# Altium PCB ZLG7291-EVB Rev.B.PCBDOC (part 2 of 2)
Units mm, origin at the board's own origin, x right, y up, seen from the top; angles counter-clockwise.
Board outline 90 x 60 mm, 2 copper layers (Top Layer, Bottom Layer); 77 components, 55 nets, 304 pads, 258 vias.
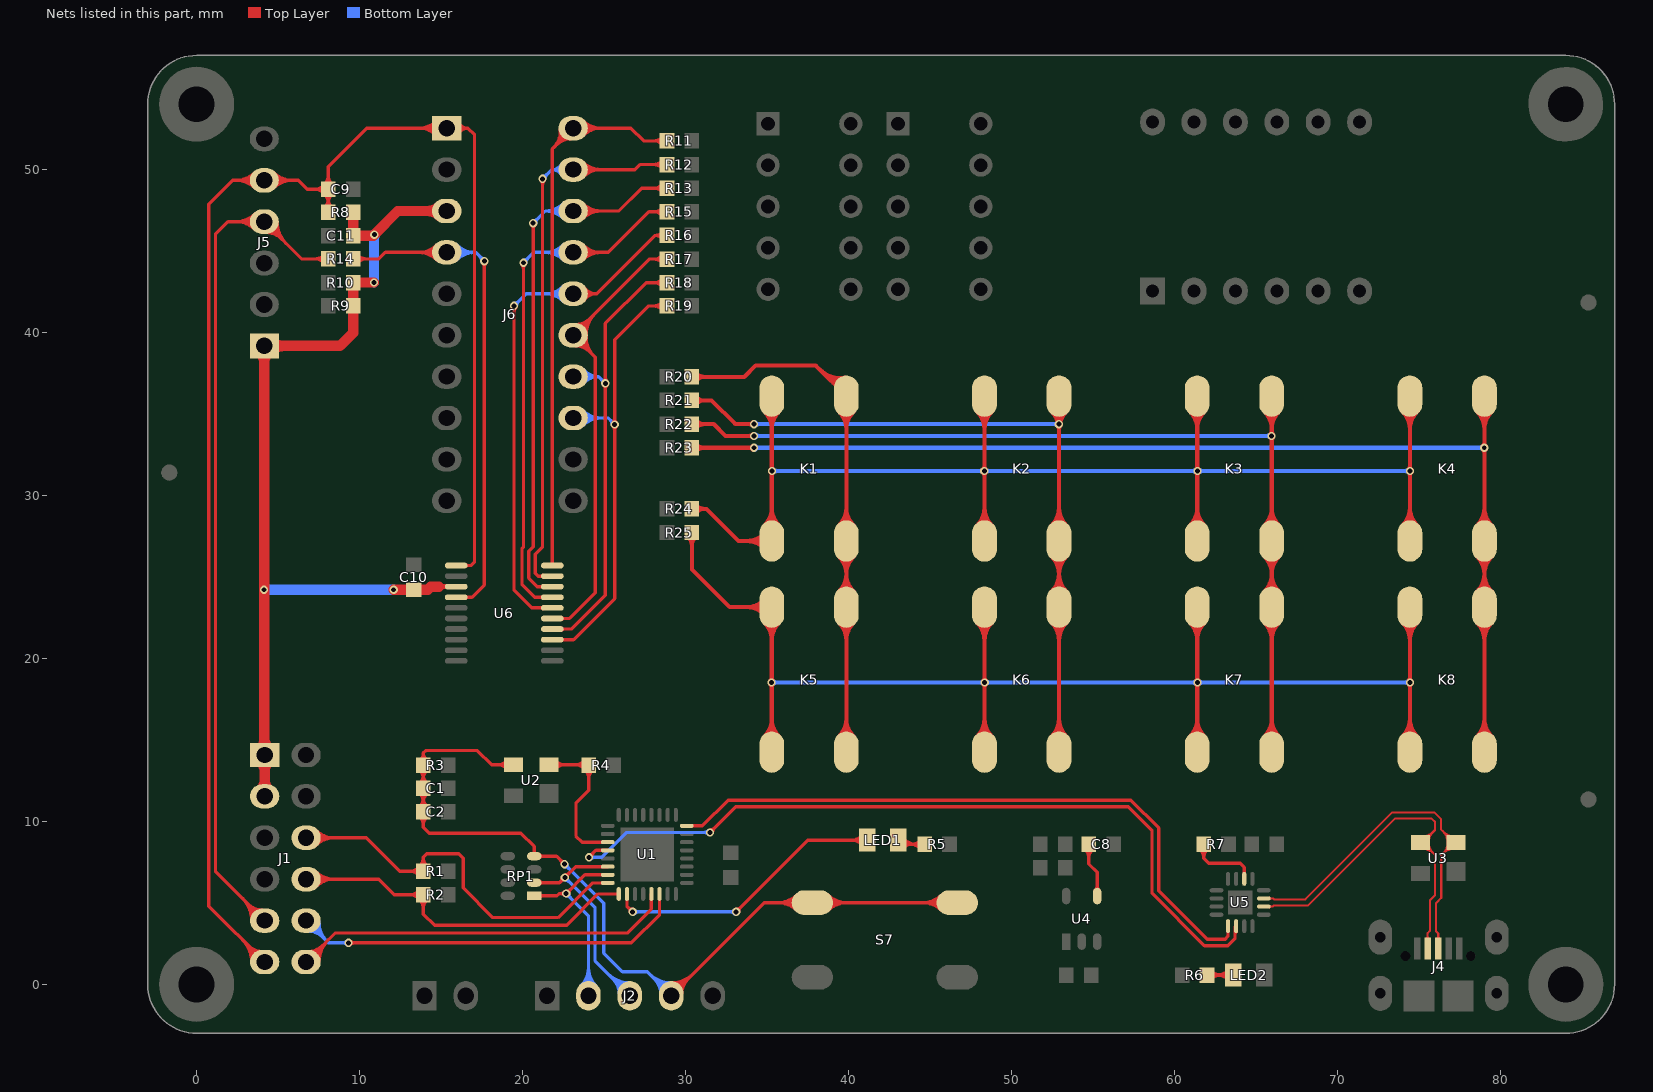
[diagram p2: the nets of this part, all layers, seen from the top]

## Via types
v1: diameter 0.508, hole 0.305, Top Layer to Bottom Layer, tented both sides, 258 vias

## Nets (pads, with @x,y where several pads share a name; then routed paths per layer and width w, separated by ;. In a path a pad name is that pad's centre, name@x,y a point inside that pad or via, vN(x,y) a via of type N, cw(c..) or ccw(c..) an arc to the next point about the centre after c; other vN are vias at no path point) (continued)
J_NRST: C1.2 C2.1 J2.4 R3.1 RP1.4 S7.2 S7.3 U2.3 | length 85.8
  Top Layer w0.203: C2.1@13.667,10.329 cw(c13.072,9.734) 13.913,9.734 cw(c14.754,9.734) C2.1@14.159,10.329 ; C2.1@13.667,10.871 ccw(c13.072,11.466) 13.913,11.466 ccw(c14.754,11.466) C2.1@14.159,10.871 ; C1.2@13.667,11.754 cw(c13.072,11.159) 13.913,11.159 cw(c14.754,11.159) C1.2@14.159,11.754 ; C1.2@13.667,12.296 ccw(c13.072,12.891) 13.913,12.891 ccw(c14.754,12.891) C1.2@14.159,12.296 ; R3.1@13.667,13.179 cw(c13.072,12.584) 13.913,12.584 cw(c14.754,12.584) R3.1@14.159,13.179 ; R3.1@13.695,13.747 ccw(c13.333,14.2) 13.913,14.2 ; R3.1@14.131,13.747 cw(c14.493,14.2) 13.913,14.2 ; U2.3@19.054,13.226 ccw(c18.447,12.619) 18.447,13.478 ccw(c18.447,14.336) U2.3@19.054,13.729 ; U2.3@19.433,13.478 18.098,13.478 17.225,14.35 14.063,14.35 13.913,14.2 ; RP1.4@20.605,7.977 ccw(c20.345,8.237) 20.713,8.237 ccw(c21.081,8.237) RP1.4@20.821,7.977 ; RP1.4@21.011,7.761 cw(c21.271,7.501) 21.271,7.869 cw(c21.271,8.237) RP1.4@21.011,7.977 ; v1@22.423,7.375 ccw(c22.055,7.375) 22.315,7.635 ccw(c22.575,7.895) v1@22.575,7.527 ; v1(22.575,7.375) 22.081,7.869 RP1.4@20.713,7.869 20.713,8.462 19.9,9.275 14.275,9.275 13.913,9.637 C2.1@13.913,10.6 C1.2@13.913,12.025 R3.1@13.913,13.45 13.913,14.2 ; J2.4@29.12,-0.7 34.831,5.011 S7.3@37.78,5.011 S7.2@46.67,5.011 ; J2.4@29.12,-0.308 ccw(c29.12,0.638) 29.789,-0.031 ; J2.4@29.12,-0.105 ccw(c29.12,1.332) 30.136,0.316 ; J2.4@29.12,0.098 ccw(c29.12,2.026) 30.483,0.663 ; J2.4@29.565,-0.55 cw(c30.278,-0.55) 29.774,-0.046 ; J2.4@29.768,-0.55 cw(c30.972,-0.55) 30.121,0.301 ; S7.3@36.805,4.544 ccw(c35.678,3.417) 35.678,5.011 ccw(c35.678,6.605) S7.3@36.805,5.478 ; S7.3@36.949,4.688 ccw(c36.168,3.907) 36.168,5.011 ccw(c36.168,6.115) S7.3@36.949,5.334 ; S7.3@38.611,4.688 cw(c39.392,3.907) 39.392,5.011 cw(c39.392,6.115) S7.3@38.611,5.334 ; S7.3@38.755,4.544 cw(c39.882,3.417) 39.882,5.011 cw(c39.882,6.605) S7.3@38.755,5.478 ; S7.2@45.695,4.544 ccw(c44.568,3.417) 44.568,5.011 ccw(c44.568,6.605) S7.2@45.695,5.478 ; S7.2@45.839,4.688 ccw(c45.058,3.907) 45.058,5.011 ccw(c45.058,6.115) S7.2@45.839,5.334
  Bottom Layer w0.203: v1@22.575,7.223 cw(c22.575,6.855) 22.835,7.115 cw(c23.095,7.375) v1@22.727,7.375 ; v1(22.575,7.375) 24.975,4.975 24.975,1.925 26.125,0.775 27.645,0.775 J2.4@29.12,-0.7 ; 27.757,0.663 ccw(c29.12,2.026) J2.4@29.12,0.098 ; 28.104,0.316 ccw(c29.12,1.332) J2.4@29.12,-0.105 ; 28.119,0.301 cw(c27.268,-0.55) J2.4@28.472,-0.55 ; 28.451,-0.031 ccw(c29.12,0.638) J2.4@29.12,-0.308 ; 28.466,-0.046 cw(c27.962,-0.55) J2.4@28.675,-0.55
KEY: J6.4 R14.2 U6.4 | length 41.4
  Top Layer w0.203: R14.2@9.6,44.51 11.185,44.51 11.585,44.91 J6.4@15.35,44.91 ; R14.2@9.847,44.264 cw(c10.442,43.669) 10.442,44.51 cw(c10.442,45.351) R14.2@9.847,44.756 ; J6.4@14.742,44.452 ccw(c13.635,43.345) 13.635,44.91 ccw(c13.635,46.475) J6.4@14.742,45.368 ; J6.4@14.885,44.595 ccw(c14.125,43.835) 14.125,44.91 ccw(c14.125,45.985) J6.4@14.885,45.225 ; U6.4@15.925,23.75 16.9,23.75 17.65,24.5 v1(17.65,44.375) ; U6.4@16.502,23.698 cw(c16.627,23.573) 16.627,23.75 cw(c16.627,23.927) U6.4@16.502,23.802 ; v1@17.542,44.267 cw(c17.282,44.007) 17.65,44.007 cw(c18.018,44.007) v1@17.758,44.267
  Bottom Layer w0.203: J6.4@15.35,44.91 17.115,44.91 v1(17.65,44.375) ; J6.4@15.815,44.595 cw(c16.575,43.835) 16.575,44.91 cw(c16.575,45.985) J6.4@15.815,45.225 ; J6.4@15.958,44.452 cw(c17.065,43.345) 17.065,44.91 cw(c17.065,46.475) J6.4@15.958,45.368 ; v1@17.498,44.375 ccw(c17.13,44.375) 17.39,44.635 ccw(c17.65,44.895) v1@17.65,44.527
KEY_INT: J1.9 J5.4 R14.1 | length 67
  Top Layer w0.203: 2.812,5.278 cw(c1.449,3.915) J1.9@3.377,3.915 ; 3.159,4.931 cw(c2.143,3.915) J1.9@3.58,3.915 ; 3.174,4.916 ccw(c4.025,5.767) J1.9@4.025,4.563 ; 3.506,4.584 cw(c2.837,3.915) J1.9@3.783,3.915 ; 3.521,4.569 ccw(c4.025,5.073) J1.9@4.025,4.36 ; J5.4@3.556,46.328 ccw(c2.429,45.201) 2.429,46.795 ccw(c2.429,48.389) J5.4@3.556,47.262 ; J5.4@3.7,46.472 ccw(c2.919,45.691) 2.919,46.795 ccw(c2.919,47.899) J5.4@3.7,47.118 ; J1.9@4.175,3.915 1.156,6.934 1.156,46.031 1.92,46.795 J5.4@4.15,46.795 6.435,44.51 R14.1@8.076,44.51 ; J5.4@4.277,46.135 cw(c4.277,44.847) 5.188,45.757 ; J5.4@4.277,46.338 cw(c4.277,45.541) 4.841,46.104 ; J5.4@4.531,46.795 ccw(c5.451,46.795) 4.8,46.145 ; J5.4@4.734,46.795 ccw(c6.145,46.795) 5.147,45.798 ; J5.4@4.937,46.795 ccw(c6.838,46.795) 5.494,45.451 ; R14.1@7.83,44.264 ccw(c7.235,43.669) 7.235,44.51 ccw(c7.235,45.351) R14.1@7.83,44.756
LED0: LED1.2 U1.10 | length 21.3
  Top Layer w0.203: U1.10@26.4,5.55 26.4,4.8 v1(26.75,4.45) ; v1@26.598,4.45 ccw(c26.23,4.45) 26.49,4.71 ccw(c26.75,4.97) v1@26.75,4.602 ; v1(33.1,4.45) 37.5,8.85 LED1.2@41.143,8.85 ; v1@33.1,4.602 ccw(c33.1,4.97) 33.36,4.71 ccw(c33.62,4.45) v1@33.252,4.45 ; LED1.2@40.856,8.563 ccw(c40.164,7.871) 40.164,8.85 ccw(c40.164,9.829) LED1.2@40.856,9.137
  Bottom Layer w0.203: v1(26.75,4.45) v1(33.1,4.45) ; v1@26.858,4.342 cw(c27.118,4.082) 27.118,4.45 cw(c27.118,4.818) v1@26.858,4.558 ; v1@32.992,4.342 ccw(c32.732,4.082) 32.732,4.45 ccw(c32.732,4.818) v1@32.992,4.558
NetC8_1: C8.1 U4.4 | length 5.3
  Top Layer w0.203: C8.1@54.492,8.317 cw(c53.897,7.722) 54.738,7.722 cw(c55.579,7.722) C8.1@54.984,8.317 ; C8.1@54.738,8.588 54.738,7.387 55.25,6.875 U4.4@55.25,5.422 ; U4.4@55.142,5.784 ccw(c54.882,6.044) 55.25,6.044 ccw(c55.618,6.044) U4.4@55.358,5.784
NetK1_1: K1.1 K1.4 K2.1 K2.4 K3.1 K3.4 K4.1 K4.4 R24.1 | length 123.1
  Top Layer w0.254: R24.1@30.387,29.175 31.275,29.175 33.245,27.205 K1.1@35.289,27.205 K1.4@35.289,36.095 ; R24.1@30.615,28.947 cw(c31.167,28.395) 31.167,29.175 cw(c31.167,29.955) R24.1@30.615,29.403 ; K1.1@34.84,26.756 ccw(c33.756,25.672) 33.756,27.205 ccw(c33.756,28.738) K1.1@34.84,27.654 ; K1.1@34.84,28.162 ccw(c33.756,29.246) 35.289,29.246 ccw(c36.822,29.246) K1.1@35.738,28.162 ; K1.4@34.84,35.138 cw(c33.756,34.054) 35.289,34.054 cw(c36.822,34.054) K1.4@35.738,35.138 ; K1.1@35.02,26.936 ccw(c34.369,26.285) 34.369,27.205 ccw(c34.369,28.125) K1.1@35.02,27.474 ; K1.1@35.02,27.982 ccw(c34.369,28.633) 35.289,28.633 ccw(c36.209,28.633) K1.1@35.558,27.982 ; K1.4@35.02,35.318 cw(c34.369,34.667) 35.289,34.667 cw(c36.209,34.667) K1.4@35.558,35.318 ; v1@35.21,31.41 cw(c35.02,31.22) 35.289,31.22 ; v1@35.21,31.59 ccw(c35.02,31.78) 35.289,31.78 ; 35.289,31.167 cw(c35.633,31.167) v1@35.39,31.41 ; 35.289,31.833 ccw(c35.633,31.833) v1@35.39,31.59 ; K2.1@47.889,28.162 ccw(c46.805,29.246) 48.338,29.246 ccw(c49.871,29.246) K2.1@48.787,28.162 ; K2.4@47.889,35.138 cw(c46.805,34.054) 48.338,34.054 cw(c49.871,34.054) K2.4@48.787,35.138 ; K2.1@48.069,27.982 ccw(c47.419,28.633) 48.338,28.633 ccw(c49.258,28.633) K2.1@48.608,27.982 ; K2.4@48.069,35.318 cw(c47.419,34.667) 48.338,34.667 cw(c49.258,34.667) K2.4@48.608,35.318 ; v1@48.235,31.41 cw(c47.986,31.161) 48.338,31.161 ; v1@48.235,31.59 ccw(c47.986,31.839) 48.338,31.839 ; K2.1@48.338,27.205 K2.4@48.338,36.095 ; 48.338,31.226 cw(c48.599,31.226) v1@48.415,31.41 ; 48.338,31.774 ccw(c48.599,31.774) v1@48.415,31.59 ; K3.1@60.939,28.162 ccw(c59.855,29.246) 61.388,29.246 ccw(c62.921,29.246) K3.1@61.837,28.162 ; K3.4@60.939,35.138 cw(c59.855,34.054) 61.388,34.054 cw(c62.921,34.054) K3.4@61.837,35.138 ; K3.1@61.118,27.982 ccw(c60.468,28.633) 61.388,28.633 ccw(c62.307,28.633) K3.1@61.657,27.982 ; K3.4@61.118,35.318 cw(c60.468,34.667) 61.388,34.667 cw(c62.307,34.667) K3.4@61.657,35.318 ; v1@61.31,31.41 cw(c61.123,31.223) 61.388,31.223 ; v1@61.31,31.59 ccw(c61.123,31.777) 61.388,31.777 ; K3.1@61.388,27.205 K3.4@61.388,36.095 ; 61.388,31.164 cw(c61.736,31.164) v1@61.49,31.41 ; 61.388,31.836 ccw(c61.736,31.836) v1@61.49,31.59 ; K4.1@73.988,28.162 ccw(c72.904,29.246) 74.437,29.246 ccw(c75.97,29.246) K4.1@74.886,28.162 ; K4.4@73.988,35.138 cw(c72.904,34.054) 74.437,34.054 cw(c75.97,34.054) K4.4@74.886,35.138 ; K4.1@74.168,27.982 ccw(c73.517,28.633) 74.437,28.633 ccw(c75.357,28.633) K4.1@74.706,27.982 ; K4.4@74.168,35.318 cw(c73.517,34.667) 74.437,34.667 cw(c75.357,34.667) K4.4@74.706,35.318 ; v1@74.347,31.41 cw(c74.13,31.193) 74.437,31.193 cw(c74.744,31.193) v1@74.527,31.41 ; v1@74.347,31.59 ccw(c74.13,31.807) 74.437,31.807 ccw(c74.744,31.807) v1@74.527,31.59 ; K4.1@74.437,27.205 v1(74.437,31.5) K4.4@74.437,36.095
  Bottom Layer w0.254: v1(35.3,31.5) v1(48.325,31.5) v1(61.4,31.5) v1(74.437,31.5) ; v1@35.39,31.41 cw(c35.607,31.193) 35.607,31.5 cw(c35.607,31.807) v1@35.39,31.59 ; v1@48.235,31.41 ccw(c48.018,31.193) 48.018,31.5 ccw(c48.018,31.807) v1@48.235,31.59 ; v1@48.415,31.41 cw(c48.632,31.193) 48.632,31.5 cw(c48.632,31.807) v1@48.415,31.59 ; v1@61.31,31.41 ccw(c61.093,31.193) 61.093,31.5 ccw(c61.093,31.807) v1@61.31,31.59 ; v1@61.49,31.41 cw(c61.707,31.193) 61.707,31.5 cw(c61.707,31.807) v1@61.49,31.59 ; v1@74.347,31.41 ccw(c74.13,31.193) 74.13,31.5 ccw(c74.13,31.807) v1@74.347,31.59
NetK1_2: K1.2 K1.3 K5.2 K5.3 R20.1 | length 60.7
  Top Layer w0.254: R20.1@30.387,37.275 33.6,37.275 34.3,37.975 37.981,37.975 K1.3@39.861,36.095 K1.2@39.861,27.205 K5.3@39.861,23.145 K5.2@39.861,14.255 ; R20.1@30.615,37.047 cw(c31.167,36.495) 31.167,37.275 cw(c31.167,38.055) R20.1@30.615,37.503 ; 38.235,37.721 ccw(c39.476,38.962) K1.3@39.759,37.23 ; 38.586,37.37 ccw(c39.575,38.359) K1.3@39.8,36.979 ; 38.936,37.02 ccw(c39.673,37.757) K1.3@39.841,36.728 ; K5.2@39.412,15.212 ccw(c38.328,16.296) 39.861,16.296 ccw(c41.394,16.296) K5.2@40.31,15.212 ; K5.3@39.412,22.188 cw(c38.328,21.104) 39.861,21.104 cw(c41.394,21.104) K5.3@40.31,22.188 ; K5.3@39.412,24.102 ccw(c38.328,25.186) 39.861,25.186 ccw(c41.394,25.186) K5.3@40.31,24.102 ; K1.2@39.412,26.248 cw(c38.328,25.164) 39.861,25.164 cw(c41.394,25.164) K1.2@40.31,26.248 ; K1.2@39.412,28.162 ccw(c38.328,29.246) 39.861,29.246 ccw(c41.394,29.246) K1.2@40.31,28.162 ; K1.3@39.412,35.138 cw(c38.328,34.054) 39.861,34.054 cw(c41.394,34.054) K1.3@40.31,35.138 ; K5.2@39.592,15.032 ccw(c38.941,15.683) 39.861,15.683 ccw(c40.781,15.683) K5.2@40.13,15.032 ; K5.3@39.592,22.368 cw(c38.941,21.717) 39.861,21.717 cw(c40.781,21.717) K5.3@40.13,22.368 ; K5.3@39.592,23.922 ccw(c38.941,24.573) 39.861,24.573 ccw(c40.781,24.573) K5.3@40.13,23.922 ; K1.2@39.592,26.428 cw(c38.941,25.777) 39.861,25.777 cw(c40.781,25.777) K1.2@40.13,26.428 ; K1.2@39.592,27.982 ccw(c38.941,28.633) 39.861,28.633 ccw(c40.781,28.633) K1.2@40.13,27.982 ; K1.3@39.592,35.318 cw(c38.941,34.667) 39.861,34.667 cw(c40.781,34.667) K1.3@40.13,35.318
NetK2_2: K2.2 K2.3 K6.2 K6.3 R21.1 | length 71.7
  Top Layer w0.254: R21.1@30.387,35.825 31.6,35.825 33.05,34.375 v1(34.2,34.375) ; R21.1@30.615,35.597 cw(c31.167,35.045) 31.167,35.825 cw(c31.167,36.605) R21.1@30.615,36.053 ; v1@34.11,34.285 ccw(c33.893,34.068) 33.893,34.375 ccw(c33.893,34.682) v1@34.11,34.465 ; K6.2@52.461,15.212 ccw(c51.377,16.296) 52.91,16.296 ccw(c54.443,16.296) K6.2@53.359,15.212 ; K6.3@52.461,22.188 cw(c51.377,21.104) 52.91,21.104 cw(c54.443,21.104) K6.3@53.359,22.188 ; K6.3@52.461,24.102 ccw(c51.377,25.186) 52.91,25.186 ccw(c54.443,25.186) K6.3@53.359,24.102 ; K2.2@52.461,26.248 cw(c51.377,25.164) 52.91,25.164 cw(c54.443,25.164) K2.2@53.359,26.248 ; K2.2@52.461,28.162 ccw(c51.377,29.246) 52.91,29.246 ccw(c54.443,29.246) K2.2@53.359,28.162 ; K2.3@52.461,35.138 cw(c51.377,34.054) 52.91,34.054 cw(c54.443,34.054) K2.3@53.359,35.138 ; K6.2@52.641,15.032 ccw(c51.991,15.683) 52.91,15.683 ccw(c53.83,15.683) K6.2@53.18,15.032 ; K6.3@52.641,22.368 cw(c51.991,21.717) 52.91,21.717 cw(c53.83,21.717) K6.3@53.18,22.368 ; K6.3@52.641,23.922 ccw(c51.991,24.573) 52.91,24.573 ccw(c53.83,24.573) K6.3@53.18,23.922 ; K2.2@52.641,26.428 cw(c51.991,25.777) 52.91,25.777 cw(c53.83,25.777) K2.2@53.18,26.428 ; K2.2@52.641,27.982 ccw(c51.991,28.633) 52.91,28.633 ccw(c53.83,28.633) K2.2@53.18,27.982 ; K2.3@52.641,35.318 cw(c51.991,34.667) 52.91,34.667 cw(c53.83,34.667) K2.3@53.18,35.318 ; v1@52.81,34.285 cw(c52.568,34.043) 52.91,34.043 ; v1@52.81,34.465 ccw(c52.568,34.707) 52.91,34.707 ; K6.2@52.91,14.255 K6.3@52.91,23.145 K2.2@52.91,27.205 K2.3@52.91,36.095 ; 52.91,34.093 cw(c53.182,34.093) v1@52.99,34.285 ; 52.91,34.657 ccw(c53.182,34.657) v1@52.99,34.465
  Bottom Layer w0.254: v1(34.2,34.375) v1(52.9,34.375) ; v1@34.29,34.285 cw(c34.507,34.068) 34.507,34.375 cw(c34.507,34.682) v1@34.29,34.465 ; v1@52.81,34.285 ccw(c52.593,34.068) 52.593,34.375 ccw(c52.593,34.682) v1@52.81,34.465
NetK3_2: K3.2 K3.3 K7.2 K7.3 R22.1 | length 84.5
  Top Layer w0.254: R22.1@30.387,34.375 31.725,34.375 32.45,33.65 v1(34.2,33.65) ; R22.1@30.615,34.147 cw(c31.167,33.595) 31.167,34.375 cw(c31.167,35.155) R22.1@30.615,34.603 ; v1@34.11,33.56 ccw(c33.893,33.343) 33.893,33.65 ccw(c33.893,33.957) v1@34.11,33.74 ; K7.2@65.511,15.212 ccw(c64.427,16.296) 65.96,16.296 ccw(c67.493,16.296) K7.2@66.409,15.212 ; K7.3@65.511,22.188 cw(c64.427,21.104) 65.96,21.104 cw(c67.493,21.104) K7.3@66.409,22.188 ; K7.3@65.511,24.102 ccw(c64.427,25.186) 65.96,25.186 ccw(c67.493,25.186) K7.3@66.409,24.102 ; K3.2@65.511,26.248 cw(c64.427,25.164) 65.96,25.164 cw(c67.493,25.164) K3.2@66.409,26.248 ; K3.2@65.511,28.162 ccw(c64.427,29.246) 65.96,29.246 ccw(c67.493,29.246) K3.2@66.409,28.162 ; K3.3@65.511,35.138 cw(c64.427,34.054) 65.96,34.054 cw(c67.493,34.054) K3.3@66.409,35.138 ; K7.2@65.69,15.032 ccw(c65.04,15.683) 65.96,15.683 ccw(c66.879,15.683) K7.2@66.229,15.032 ; K7.3@65.69,22.368 cw(c65.04,21.717) 65.96,21.717 cw(c66.879,21.717) K7.3@66.229,22.368 ; K7.3@65.69,23.922 ccw(c65.04,24.573) 65.96,24.573 ccw(c66.879,24.573) K7.3@66.229,23.922 ; K3.2@65.69,26.428 cw(c65.04,25.777) 65.96,25.777 cw(c66.879,25.777) K3.2@66.229,26.428 ; K3.2@65.69,27.982 ccw(c65.04,28.633) 65.96,28.633 ccw(c66.879,28.633) K3.2@66.229,27.982 ; K3.3@65.69,35.318 cw(c65.04,34.667) 65.96,34.667 cw(c66.879,34.667) K3.3@66.229,35.318 ; v1@65.86,33.56 cw(c65.62,33.32) 65.96,33.32 ; v1@65.86,33.74 ccw(c65.62,33.98) 65.96,33.98 ; K7.2@65.96,14.255 K7.3@65.96,23.145 K3.2@65.96,27.205 K3.3@65.96,36.095 ; 65.96,33.367 cw(c66.233,33.367) v1@66.04,33.56 ; 65.96,33.933 ccw(c66.233,33.933) v1@66.04,33.74
  Bottom Layer w0.254: v1(34.2,33.65) v1(65.95,33.65) ; v1@34.29,33.56 cw(c34.507,33.343) 34.507,33.65 cw(c34.507,33.957) v1@34.29,33.74 ; v1@65.86,33.56 ccw(c65.643,33.343) 65.643,33.65 ccw(c65.643,33.957) v1@65.86,33.74
NetK4_2: K4.2 K4.3 K8.2 K8.3 R23.1 | length 97.2
  Top Layer w0.254: R23.1@30.387,32.925 v1(34.2,32.925) ; R23.1@30.615,32.697 cw(c31.167,32.145) 31.167,32.925 cw(c31.167,33.705) R23.1@30.615,33.153 ; v1@34.11,32.835 ccw(c33.893,32.618) 33.893,32.925 ccw(c33.893,33.232) v1@34.11,33.015 ; K8.2@78.56,15.212 ccw(c77.476,16.296) 79.009,16.296 ccw(c80.542,16.296) K8.2@79.458,15.212 ; K8.3@78.56,22.188 cw(c77.476,21.104) 79.009,21.104 cw(c80.542,21.104) K8.3@79.458,22.188 ; K8.3@78.56,24.102 ccw(c77.476,25.186) 79.009,25.186 ccw(c80.542,25.186) K8.3@79.458,24.102 ; K4.2@78.56,26.248 cw(c77.476,25.164) 79.009,25.164 cw(c80.542,25.164) K4.2@79.458,26.248 ; K4.2@78.56,28.162 ccw(c77.476,29.246) 79.009,29.246 ccw(c80.542,29.246) K4.2@79.458,28.162 ; K4.3@78.56,35.138 cw(c77.476,34.054) 79.009,34.054 cw(c80.542,34.054) K4.3@79.458,35.138 ; K8.2@78.74,15.032 ccw(c78.089,15.683) 79.009,15.683 ccw(c79.929,15.683) K8.2@79.278,15.032 ; K8.3@78.74,22.368 cw(c78.089,21.717) 79.009,21.717 cw(c79.929,21.717) K8.3@79.278,22.368 ; K8.3@78.74,23.922 ccw(c78.089,24.573) 79.009,24.573 ccw(c79.929,24.573) K8.3@79.278,23.922 ; K4.2@78.74,26.428 cw(c78.089,25.777) 79.009,25.777 cw(c79.929,25.777) K4.2@79.278,26.428 ; K4.2@78.74,27.982 ccw(c78.089,28.633) 79.009,28.633 ccw(c79.929,28.633) K4.2@79.278,27.982 ; K4.3@78.74,35.318 cw(c78.089,34.667) 79.009,34.667 cw(c79.929,34.667) K4.3@79.278,35.318 ; v1@78.91,32.835 cw(c78.672,32.597) 79.009,32.597 ; v1@78.91,33.015 ccw(c78.672,33.253) 79.009,33.253 ; K8.2@79.009,14.255 K8.3@79.009,23.145 K4.2@79.009,27.205 K4.3@79.009,36.095 ; 79.009,32.64 cw(c79.285,32.64) v1@79.09,32.835 ; 79.009,33.21 ccw(c79.285,33.21) v1@79.09,33.015
  Bottom Layer w0.254: v1(34.2,32.925) v1(79,32.925) ; v1@34.29,32.835 cw(c34.507,32.618) 34.507,32.925 cw(c34.507,33.232) v1@34.29,33.015 ; v1@78.91,32.835 ccw(c78.693,32.618) 78.693,32.925 ccw(c78.693,33.232) v1@78.91,33.015
NetK5_1: K5.1 K5.4 K6.1 K6.4 K7.1 K7.4 K8.1 K8.4 R25.1 | length 125.5
  Top Layer w0.254: R25.1@30.159,27.472 cw(c29.607,26.92) 30.387,26.92 cw(c31.167,26.92) R25.1@30.615,27.472 ; R25.1@30.387,27.725 30.387,25.463 32.705,23.145 K5.4@35.289,23.145 K5.1@35.289,14.255 ; K5.1@34.84,15.212 ccw(c33.756,16.296) 35.289,16.296 ccw(c36.822,16.296) K5.1@35.738,15.212 ; K5.4@34.84,22.188 cw(c33.756,21.104) 35.289,21.104 cw(c36.822,21.104) K5.4@35.738,22.188 ; K5.4@34.84,22.696 ccw(c33.756,21.612) 33.756,23.145 ccw(c33.756,24.678) K5.4@34.84,23.594 ; K5.1@35.02,15.032 ccw(c34.369,15.683) 35.289,15.683 ccw(c36.209,15.683) K5.1@35.558,15.032 ; K5.4@35.02,22.368 cw(c34.369,21.717) 35.289,21.717 cw(c36.209,21.717) K5.4@35.558,22.368 ; K5.4@35.02,22.876 ccw(c34.369,22.225) 34.369,23.145 ccw(c34.369,24.065) K5.4@35.02,23.414 ; v1@35.185,18.435 cw(c34.935,18.185) 35.289,18.185 ; v1@35.185,18.615 ccw(c34.935,18.865) 35.289,18.865 ; 35.289,18.252 cw(c35.548,18.252) v1@35.365,18.435 ; 35.289,18.798 ccw(c35.548,18.798) v1@35.365,18.615 ; K6.1@47.889,15.212 ccw(c46.805,16.296) 48.338,16.296 ccw(c49.871,16.296) K6.1@48.787,15.212 ; K6.4@47.889,22.188 cw(c46.805,21.104) 48.338,21.104 cw(c49.871,21.104) K6.4@48.787,22.188 ; K6.1@48.069,15.032 ccw(c47.419,15.683) 48.338,15.683 ccw(c49.258,15.683) K6.1@48.608,15.032 ; K6.4@48.069,22.368 cw(c47.419,21.717) 48.338,21.717 cw(c49.258,21.717) K6.4@48.608,22.368 ; v1@48.26,18.435 cw(c48.072,18.247) 48.338,18.247 ; v1@48.26,18.615 ccw(c48.072,18.803) 48.338,18.803 ; K6.1@48.338,14.255 K6.4@48.338,23.145 ; 48.338,18.19 cw(c48.685,18.19) v1@48.44,18.435 ; 48.338,18.86 ccw(c48.685,18.86) v1@48.44,18.615 ; K7.1@60.939,15.212 ccw(c59.855,16.296) 61.388,16.296 ccw(c62.921,16.296) K7.1@61.837,15.212 ; K7.4@60.939,22.188 cw(c59.855,21.104) 61.388,21.104 cw(c62.921,21.104) K7.4@61.837,22.188 ; K7.1@61.118,15.032 ccw(c60.468,15.683) 61.388,15.683 ccw(c62.307,15.683) K7.1@61.657,15.032 ; K7.4@61.118,22.368 cw(c60.468,21.717) 61.388,21.717 cw(c62.307,21.717) K7.4@61.657,22.368 ; v1@61.31,18.435 cw(c61.123,18.248) 61.388,18.248 ; v1@61.31,18.615 ccw(c61.123,18.802) 61.388,18.802 ; K7.1@61.388,14.255 K7.4@61.388,23.145 ; 61.388,18.189 cw(c61.736,18.189) v1@61.49,18.435 ; 61.388,18.861 ccw(c61.736,18.861) v1@61.49,18.615 ; K8.1@73.988,15.212 ccw(c72.904,16.296) 74.437,16.296 ccw(c75.97,16.296) K8.1@74.886,15.212 ; K8.4@73.988,22.188 cw(c72.904,21.104) 74.437,21.104 cw(c75.97,21.104) K8.4@74.886,22.188 ; K8.1@74.168,15.032 ccw(c73.517,15.683) 74.437,15.683 ccw(c75.357,15.683) K8.1@74.706,15.032 ; K8.4@74.168,22.368 cw(c73.517,21.717) 74.437,21.717 cw(c75.357,21.717) K8.4@74.706,22.368 ; v1@74.347,18.435 cw(c74.13,18.218) 74.437,18.218 cw(c74.744,18.218) v1@74.527,18.435 ; v1@74.347,18.615 ccw(c74.13,18.832) 74.437,18.832 ccw(c74.744,18.832) v1@74.527,18.615 ; K8.1@74.437,14.255 v1(74.437,18.525) K8.4@74.437,23.145
  Bottom Layer w0.254: v1(35.275,18.525) v1(48.35,18.525) v1(61.4,18.525) v1(74.437,18.525) ; v1@35.365,18.435 cw(c35.582,18.218) 35.582,18.525 cw(c35.582,18.832) v1@35.365,18.615 ; v1@48.26,18.435 ccw(c48.043,18.218) 48.043,18.525 ccw(c48.043,18.832) v1@48.26,18.615 ; v1@48.44,18.435 cw(c48.657,18.218) 48.657,18.525 cw(c48.657,18.832) v1@48.44,18.615 ; v1@61.31,18.435 ccw(c61.093,18.218) 61.093,18.525 ccw(c61.093,18.832) v1@61.31,18.615 ; v1@61.49,18.435 cw(c61.707,18.218) 61.707,18.525 cw(c61.707,18.832) v1@61.49,18.615 ; v1@74.347,18.435 ccw(c74.13,18.218) 74.13,18.525 ccw(c74.13,18.832) v1@74.347,18.615
NetLED1_1: LED1.1 R5.2 | length 5.1
  Top Layer w0.203: LED1.1@43.057,8.85 43.319,8.588 R5.2@44.663,8.588 ; LED1.1@43.2,8.8 ccw(c43.712,9.312) 43.712,8.588 ; LED1.1@43.344,8.37 cw(c43.869,7.845) 43.869,8.588 ; LED1.1@43.344,8.944 ccw(c44.203,9.803) 44.203,8.588 ; R5.2@44.417,8.342 ccw(c43.822,7.747) 43.822,8.588 ccw(c43.822,9.429) R5.2@44.417,8.834
NetLED2_1: LED2.1 R6.2 | length 4.5
  Top Layer w0.203: R6.2@61.987,0.575 LED2.1@63.593,0.575 ; R6.2@62.233,0.329 cw(c62.828,-0.266) 62.828,0.575 cw(c62.828,1.416) R6.2@62.233,0.821 ; LED2.1@63.306,0.288 ccw(c62.614,-0.404) 62.614,0.575 ccw(c62.614,1.554) LED2.1@63.306,0.862
NetR7_1: R7.1 U5.2 | length 5.6
  Top Layer w0.203: R7.1@61.545,8.313 cw(c60.983,7.737) 61.788,7.737 ; R7.1@61.788,8.588 61.788,7.737 ; R7.1@62.031,8.313 ccw(c62.593,7.737) 61.788,7.737 ; U5.2@64.275,6.475 64.275,7.175 64.025,7.425 62.1,7.425 61.788,7.737
NRST: C9.1 J1.11 J5.5 J6.1 R8.1 U6.1 | length 121.9
  Top Layer w0.203: 2.812,2.738 cw(c1.449,1.375) J1.11@3.377,1.375 ; 3.159,2.391 cw(c2.143,1.375) J1.11@3.58,1.375 ; 3.174,2.376 ccw(c4.025,3.227) J1.11@4.025,2.023 ; 3.506,2.044 cw(c2.837,1.375) J1.11@3.783,1.375 ; 3.521,2.029 ccw(c4.025,2.533) J1.11@4.025,1.82 ; J5.5@3.556,48.868 ccw(c2.429,47.741) 2.429,49.335 ccw(c2.429,50.929) J5.5@3.556,49.802 ; J5.5@3.7,49.012 ccw(c2.919,48.231) 2.919,49.335 ccw(c2.919,50.439) J5.5@3.7,49.658 ; J1.11@4.175,1.375 0.75,4.8 0.75,47.875 2.21,49.335 J5.5@4.15,49.335 6.24,49.335 6.79,48.785 C9.1@8.076,48.785 ; J5.5@4.6,49.012 cw(c5.381,48.231) 5.381,49.335 cw(c5.381,50.439) J5.5@4.6,49.658 ; J5.5@4.744,48.868 cw(c5.871,47.741) 5.871,49.335 cw(c5.871,50.929) J5.5@4.744,49.802 ; R8.1@7.83,47.631 ccw(c7.235,48.226) 8.076,48.226 ccw(c8.918,48.226) R8.1@8.323,47.631 ; C9.1@7.83,48.514 cw(c7.235,47.919) 8.076,47.919 cw(c8.918,47.919) C9.1@8.323,48.514 ; C9.1@7.83,48.539 ccw(c7.235,47.944) 7.235,48.785 ccw(c7.235,49.626) C9.1@7.83,49.031 ; C9.1@7.83,49.056 ccw(c7.235,49.651) 8.076,49.651 ccw(c8.918,49.651) C9.1@8.323,49.056 ; R8.1@8.076,47.36 C9.1@8.076,48.785 ; J6.1@14.742,52.072 ccw(c13.635,50.965) 13.635,52.53 ccw(c13.635,54.095) J6.1@14.742,52.988 ; J6.1@14.885,52.215 ccw(c14.125,51.455) 14.125,52.53 ccw(c14.125,53.605) J6.1@14.885,52.845 ; J6.1@15.882,52.301 cw(c16.286,52.059) 16.286,52.53 cw(c16.286,53.001) J6.1@15.882,52.759 ; U6.1@15.925,25.7 16.825,25.7 17.05,25.925 17.05,52.125 16.645,52.53 ; J6.1@16.056,52.197 cw(c16.645,51.843) 16.645,52.53 ; J6.1@16.056,52.863 ccw(c16.645,53.217) 16.645,52.53 ; U6.1@16.502,25.648 cw(c16.627,25.523) 16.627,25.7 cw(c16.627,25.877) U6.1@16.502,25.752 ; C9.1@8.076,48.785 8.076,50.176 10.43,52.53 J6.1@15.35,52.53 16.645,52.53
PIO0_24: J1.10 U1.14 | length 30
  Top Layer w0.203: v1(9.325,2.55) 26.675,2.55 28.4,4.275 U1.14@28.4,5.55 ; v1@9.433,2.442 cw(c9.693,2.182) 9.693,2.55 cw(c9.693,2.918) v1@9.433,2.658
  Bottom Layer w0.203: J1.10@6.715,3.915 8.08,2.55 v1(9.325,2.55) ; J1.10@6.865,3.267 cw(c6.865,2.063) 7.716,2.914 ; J1.10@6.865,3.47 cw(c6.865,2.757) 7.369,3.261 ; J1.10@7.107,3.905 ccw(c7.941,3.87) 7.351,3.28 ; J1.10@7.31,3.896 ccw(c8.569,3.843) 7.678,2.952 ; J1.10@7.513,3.888 ccw(c9.197,3.817) 8.005,2.625 ; v1@9.217,2.442 ccw(c8.957,2.182) 8.957,2.55 ccw(c8.957,2.918) v1@9.217,2.658
PIO0_25: J1.12 U1.13 | length 28.3
  Top Layer w0.203: J1.12@6.715,1.375 8.49,3.15 26.425,3.15 27.9,4.625 U1.13@27.9,5.55 ; J1.12@6.865,1.82 ccw(c6.865,2.533) 7.369,2.029 ; J1.12@6.865,2.023 ccw(c6.865,3.227) 7.716,2.376 ; J1.12@7.107,1.375 cw(c8.053,1.375) 7.384,2.044 ; J1.12@7.31,1.375 cw(c8.747,1.375) 7.731,2.391 ; J1.12@7.513,1.375 cw(c9.441,1.375) 8.078,2.738
R\E\S\E\T\: R4.2 U1.3 U2.2 | length 13.2
  Top Layer w0.203: U2.2@21.617,13.478 R4.2@24.036,13.478 ; U2.2@21.996,13.226 cw(c22.603,12.619) 22.603,13.478 cw(c22.603,14.336) U2.2@21.996,13.729 ; 23.216,13.478 cw(c23.216,12.628) R4.2@23.817,13.229 ; 23.228,13.478 ccw(c23.228,14.31) R4.2@23.817,13.721 ; R4.2@23.817,13.179 cw(c23.222,12.584) 24.063,12.584 cw(c24.904,12.584) R4.2@24.309,13.179 ; R4.2@24.063,13.45 24.063,11.9 23.275,11.112 23.275,9.1 23.65,8.725 U1.3@25.225,8.725
  Top Layer w0.254: R4.2@24.036,13.478 R4.2@24.063,13.45
SCL: J1.8 R2.1 U1.9 | length 28.6
  Top Layer w0.203: J1.8@6.715,6.455 11.17,6.455 12.125,5.5 R2.1@13.913,5.5 13.913,4.312 14.6,3.625 22.7,3.625 24.625,5.55 U1.9@25.9,5.55 ; J1.8@7.18,6.14 cw(c7.94,5.38) 7.94,6.455 cw(c7.94,7.53) J1.8@7.18,6.77 ; J1.8@7.323,5.997 cw(c8.43,4.89) 8.43,6.455 cw(c8.43,8.02) J1.8@7.323,6.913 ; R2.1@13.667,5.229 cw(c13.072,4.634) 13.913,4.634 cw(c14.754,4.634) R2.1@14.159,5.229 ; R2.1@13.667,5.254 ccw(c13.072,4.659) 13.072,5.5 ccw(c13.072,6.341) R2.1@13.667,5.746
SDA: J1.6 R1.1 U1.8 | length 30.7
  Top Layer w0.203: J1.6@6.715,8.995 10.405,8.995 12.45,6.95 R1.1@13.913,6.95 13.913,7.813 ; J1.6@7.18,8.68 cw(c7.94,7.92) 7.94,8.995 cw(c7.94,10.07) J1.6@7.18,9.31 ; J1.6@7.323,8.537 cw(c8.43,7.43) 8.43,8.995 cw(c8.43,10.56) J1.6@7.323,9.453 ; R1.1@13.667,6.704 ccw(c13.072,6.109) 13.072,6.95 ccw(c13.072,7.791) R1.1@13.667,7.196 ; R1.1@13.667,7.222 ccw(c13.08,7.813) 13.913,7.813 ; R1.1@14.159,7.222 cw(c14.746,7.813) 13.913,7.813 ; U1.8@25.225,6.225 24.3,6.225 22.175,4.1 18.175,4.1 16.35,5.925 16.35,7.75 16.075,8.025 14.125,8.025 13.913,7.813
SEG0: J6.13 R19.1 U6.13 | length 35
  Top Layer w0.203: U6.13@21.825,21.15 23.125,21.15 25.65,23.675 v1(25.65,34.35) 25.65,39.55 27.725,41.625 R19.1@28.863,41.625 ; U6.13@22.402,21.098 cw(c22.527,20.973) 22.527,21.15 cw(c22.527,21.327) U6.13@22.402,21.202 ; v1@25.542,34.242 cw(c25.282,33.982) 25.65,33.982 cw(c26.018,33.982) v1@25.758,34.242 ; v1@25.542,34.458 ccw(c25.282,34.718) 25.65,34.718 ccw(c26.018,34.718) v1@25.758,34.458 ; R19.1@28.617,41.379 ccw(c28.022,40.784) 28.022,41.625 ccw(c28.022,42.466) R19.1@28.617,41.871
  Bottom Layer w0.203: J6.13@23.1,34.75 25.25,34.75 v1(25.65,34.35) ; J6.13@23.565,34.435 cw(c24.325,33.675) 24.325,34.75 cw(c24.325,35.825) J6.13@23.565,35.065 ; J6.13@23.708,34.292 cw(c24.815,33.185) 24.815,34.75 cw(c24.815,36.315) J6.13@23.708,35.208 ; v1@25.498,34.35 ccw(c25.13,34.35) 25.39,34.61 ccw(c25.65,34.87) v1@25.65,34.502
SEG1: J6.14 R18.1 U6.14 | length 34.6
  Top Layer w0.203: U6.14@21.825,21.8 22.994,21.8 25.075,23.881 v1(25.075,36.875) 25.075,40.55 27.575,43.05 R18.1@28.863,43.05 ; U6.14@22.402,21.748 cw(c22.527,21.623) 22.527,21.8 cw(c22.527,21.977) U6.14@22.402,21.852 ; v1@24.967,36.767 cw(c24.707,36.507) 25.075,36.507 cw(c25.443,36.507) v1@25.183,36.767 ; v1@24.967,36.983 ccw(c24.707,37.243) 25.075,37.243 ccw(c25.443,37.243) v1@25.183,36.983 ; R18.1@28.617,42.804 ccw(c28.022,42.209) 28.022,43.05 ccw(c28.022,43.891) R18.1@28.617,43.296
  Bottom Layer w0.203: J6.14@23.1,37.29 24.66,37.29 ; J6.14@23.588,37 cw(c24.218,36.46) 24.218,37.29 cw(c24.218,38.12) J6.14@23.588,37.58 ; J6.14@23.742,36.868 cw(c24.66,36.081) 24.66,37.29 ; J6.14@23.742,37.712 ccw(c24.66,38.499) 24.66,37.29 ; v1@24.923,36.875 ccw(c24.555,36.875) 24.815,37.135 ccw(c25.075,37.395) v1@25.075,37.027 ; v1(25.075,36.875) 24.66,37.29
SEG2: J6.15 R17.1 U6.15 | length 38.4
  Top Layer w0.203: U6.15@21.825,22.45 22.882,22.45 24.45,24.018 24.45,38.48 J6.15@23.1,39.83 27.77,44.5 R17.1@28.863,44.5 ; U6.15@22.402,22.398 cw(c22.527,22.273) 22.527,22.45 cw(c22.527,22.627) U6.15@22.402,22.502 ; J6.15@23.25,39.182 cw(c23.25,37.978) 24.101,38.829 ; J6.15@23.25,39.385 cw(c23.25,38.672) 23.754,39.176 ; J6.15@23.25,40.275 ccw(c23.25,40.988) 23.754,40.484 ; J6.15@23.25,40.478 ccw(c23.25,41.682) 24.101,40.831 ; J6.15@23.492,39.818 ccw(c24.303,39.776) 23.729,39.201 ; J6.15@23.492,39.83 cw(c24.438,39.83) 23.769,40.499 ; J6.15@23.695,39.807 ccw(c24.918,39.744) 24.052,38.878 ; J6.15@23.695,39.83 cw(c25.132,39.83) 24.116,40.846 ; J6.15@23.898,39.797 ccw(c25.533,39.713) 24.375,38.555 ; J6.15@23.898,39.83 cw(c25.826,39.83) 24.463,41.193 ; R17.1@28.617,44.254 ccw(c28.022,43.659) 28.022,44.5 ccw(c28.022,45.341) R17.1@28.617,44.746
SEG3: J6.16 R16.1 U6.16 | length 41.1
  Top Layer w0.203: v1@19.367,41.523 cw(c19.107,41.263) 19.475,41.263 cw(c19.843,41.263) v1@19.583,41.523 ; v1(19.475,41.631) 19.475,24.175 20.55,23.1 U6.16@21.825,23.1 ; U6.16@21.248,23.048 ccw(c21.123,22.923) 21.123,23.1 ccw(c21.123,23.277) U6.16@21.248,23.152 ; J6.16@23.1,42.37 24.545,42.37 ; J6.16@23.606,42.103 cw(c24.139,41.705) 24.139,42.37 cw(c24.139,43.035) J6.16@23.606,42.637 ; J6.16@23.769,41.982 cw(c24.545,41.401) 24.545,42.37 ; J6.16@23.769,42.758 ccw(c24.545,43.339) 24.545,42.37 ; R16.1@28.594,45.729 ccw(c28.125,45.343) 28.125,45.95 ; R16.1@28.594,46.171 cw(c28.125,46.557) 28.125,45.95 ; R16.1@28.863,45.95 28.125,45.95 ; 24.545,42.37 28.125,45.95
  Bottom Layer w0.203: v1(19.475,41.631) 20.214,42.37 J6.16@23.1,42.37 ; v1@19.475,41.783 ccw(c19.475,42.151) 19.735,41.891 ccw(c19.995,41.631) v1@19.627,41.631 ; J6.16@22.492,41.912 ccw(c21.385,40.805) 21.385,42.37 ccw(c21.385,43.935) J6.16@22.492,42.828 ; J6.16@22.635,42.055 ccw(c21.875,41.295) 21.875,42.37 ccw(c21.875,43.445) J6.16@22.635,42.685
SEG4: J6.17 R15.1 U6.17 | length 43.1
  Top Layer w0.203: v1@19.942,44.167 cw(c19.682,43.907) 20.05,43.907 cw(c20.418,43.907) v1@20.158,44.167 ; v1(20.05,44.275) 20.05,26.824 19.962,26.737 19.962,24.538 20.75,23.75 U6.17@21.825,23.75 ; U6.17@21.248,23.698 ccw(c21.123,23.573) 21.123,23.75 ccw(c21.123,23.927) U6.17@21.248,23.802 ; J6.17@23.1,44.91 25.26,44.91 27.75,47.4 R15.1@28.863,47.4 ; J6.17@23.565,44.595 cw(c24.325,43.835) 24.325,44.91 cw(c24.325,45.985) J6.17@23.565,45.225 ; J6.17@23.708,44.452 cw(c24.815,43.345) 24.815,44.91 cw(c24.815,46.475) J6.17@23.708,45.368 ; R15.1@28.617,47.154 ccw(c28.022,46.559) 28.022,47.4 ccw(c28.022,48.241) R15.1@28.617,47.646
  Bottom Layer w0.203: v1(20.05,44.275) 20.685,44.91 J6.17@23.1,44.91 ; v1@20.05,44.427 ccw(c20.05,44.795) 20.31,44.535 ccw(c20.57,44.275) v1@20.202,44.275 ; J6.17@22.492,44.452 ccw(c21.385,43.345) 21.385,44.91 ccw(c21.385,46.475) J6.17@22.492,45.368 ; J6.17@22.635,44.595 ccw(c21.875,43.835) 21.875,44.91 ccw(c21.875,45.985) J6.17@22.635,45.225
SEG5: J6.18 R13.1 U6.18 | length 43.7
  Top Layer w0.203: v1@20.542,46.592 cw(c20.282,46.332) 20.65,46.332 cw(c21.018,46.332) v1@20.758,46.592 ; v1(20.65,46.7) 20.65,26.85 20.369,26.568 20.369,24.931 20.9,24.4 U6.18@21.825,24.4 ; U6.18@21.248,24.348 ccw(c21.123,24.223) 21.123,24.4 ccw(c21.123,24.577) U6.18@21.248,24.452 ; J6.18@23.1,47.45 25.9,47.45 27.3,48.85 R13.1@28.863,48.85 ; J6.18@23.565,47.135 cw(c24.325,46.375) 24.325,47.45 cw(c24.325,48.525) J6.18@23.565,47.765 ; J6.18@23.708,46.992 cw(c24.815,45.885) 24.815,47.45 cw(c24.815,49.015) J6.18@23.708,47.908 ; R13.1@28.617,48.604 ccw(c28.022,48.009) 28.022,48.85 ccw(c28.022,49.691) R13.1@28.617,49.096
  Bottom Layer w0.203: v1(20.65,46.7) 21.4,47.45 ; v1@20.65,46.852 ccw(c20.65,47.22) 20.91,46.96 ccw(c21.17,46.7) v1@20.802,46.7 ; J6.18@22.488,46.995 ccw(c21.4,45.922) 21.4,47.45 ; J6.18@22.488,47.905 cw(c21.4,48.978) 21.4,47.45 ; J6.18@22.633,47.137 ccw(c21.886,46.401) 21.886,47.45 ccw(c21.886,48.499) J6.18@22.633,47.763 ; J6.18@23.1,47.45 21.4,47.45
SEG6: J6.19 R12.1 U6.19 | length 42.9
  Top Layer w0.203: v1@21.117,49.317 cw(c20.857,49.057) 21.225,49.057 cw(c21.593,49.057) v1@21.333,49.317 ; v1(21.225,49.425) 21.225,26.85 20.775,26.4 20.775,25.225 20.95,25.05 U6.19@21.825,25.05 ; U6.19@21.248,24.998 ccw(c21.123,24.873) 21.123,25.05 ccw(c21.123,25.227) U6.19@21.248,25.102 ; J6.19@23.1,49.99 26.89,49.99 27.2,50.3 R12.1@28.863,50.3 ; J6.19@23.565,49.675 cw(c24.325,48.915) 24.325,49.99 cw(c24.325,51.065) J6.19@23.565,50.305 ; J6.19@23.708,49.532 cw(c24.815,48.425) 24.815,49.99 cw(c24.815,51.555) J6.19@23.708,50.448 ; R12.1@28.617,50.054 ccw(c28.022,49.459) 28.022,50.3 ccw(c28.022,51.141) R12.1@28.617,50.546
  Bottom Layer w0.203: v1(21.225,49.425) 21.79,49.99 J6.19@23.1,49.99 ; v1@21.225,49.577 ccw(c21.225,49.945) 21.485,49.685 ccw(c21.745,49.425) v1@21.377,49.425 ; J6.19@22.398,49.65 ccw(c21.79,49.277) 21.79,49.99 ccw(c21.79,50.703) J6.19@22.398,50.33 ; J6.19@22.571,49.757 ccw(c22.154,49.5) 22.154,49.99 ccw(c22.154,50.48) J6.19@22.571,50.223
SEG7: J6.20 R11.1 U6.20 | length 42.9
  Top Layer w0.203: U6.20@21.773,25.752 ccw(c21.648,25.877) 21.825,25.877 ccw(c22.002,25.877) U6.20@21.877,25.752 ; U6.20@21.825,25.7 21.825,51.255 J6.20@23.1,52.53 26.645,52.53 27.425,51.75 R11.1@28.863,51.75 ; 21.9,51.33 ccw(c20.906,52.324) J6.20@22.305,52.465 ; 22.099,51.529 cw(c22.95,50.678) J6.20@22.95,51.882 ; 22.203,51.633 ccw(c21.456,52.38) J6.20@22.507,52.485 ; 22.446,51.876 cw(c22.95,51.372) J6.20@22.95,52.085 ; J6.20@23.565,52.215 cw(c24.325,51.455) 24.325,52.53 cw(c24.325,53.605) J6.20@23.565,52.845 ; J6.20@23.708,52.072 cw(c24.815,50.965) 24.815,52.53 cw(c24.815,54.095) J6.20@23.708,52.988 ; R11.1@28.617,51.504 ccw(c28.022,50.909) 28.022,51.75 ccw(c28.022,52.591) R11.1@28.617,51.996
SWD_CLK: J2.3 RP1.2 U1.6 | length 21
  Top Layer w0.203: RP1.2@20.713,6.244 22.269,6.244 v1(22.588,6.563) 23.25,7.225 U1.6@25.225,7.225 ; RP1.2@21.011,6.136 cw(c21.271,5.876) 21.271,6.244 cw(c21.271,6.612) RP1.2@21.011,6.351 ; v1@22.435,6.563 cw(c22.067,6.563) 22.327,6.302 cw(c22.588,6.042) v1@22.588,6.41 ; v1@22.588,6.715 ccw(c22.588,7.083) 22.848,6.823 ccw(c23.108,6.563) v1@22.74,6.563
  Bottom Layer w0.203: v1@22.588,6.41 cw(c22.588,6.042) 22.848,6.302 cw(c23.108,6.563) v1@22.74,6.563 ; v1(22.588,6.563) 24.446,4.704 24.446,1.434 J2.3@26.58,-0.7 ; 25.217,0.663 ccw(c26.58,2.026) J2.3@26.58,0.098 ; 25.564,0.316 ccw(c26.58,1.332) J2.3@26.58,-0.105 ; 25.579,0.301 cw(c24.728,-0.55) J2.3@25.932,-0.55 ; 25.911,-0.031 ccw(c26.58,0.638) J2.3@26.58,-0.308 ; 25.926,-0.046 cw(c25.422,-0.55) J2.3@26.135,-0.55
SWD_IO: J2.2 RP1.1 U1.7 | length 18.3
  Top Layer w0.203: RP1.1@20.713,5.431 22.1,5.431 22.244,5.575 v1(22.675,5.575) 23.825,6.725 U1.7@25.225,6.725 ; RP1.1@21.011,5.323 cw(c21.271,5.063) 21.271,5.431 cw(c21.271,5.799) RP1.1@21.011,5.539 ; v1@22.567,5.467 ccw(c22.307,5.207) 22.307,5.575 ccw(c22.307,5.943) v1@22.567,5.683 ; v1@22.675,5.727 ccw(c22.675,6.095) 22.935,5.835 ccw(c23.195,5.575) v1@22.827,5.575
  Bottom Layer w0.203: v1@22.675,5.423 cw(c22.675,5.055) 22.935,5.315 cw(c23.195,5.575) v1@22.827,5.575 ; v1(22.675,5.575) 24.04,4.21 J2.2@24.04,-0.7 ; J2.2@23.582,-0.092 ccw(c22.475,1.015) 24.04,1.015 ccw(c25.605,1.015) J2.2@24.498,-0.092 ; J2.2@23.725,-0.235 ccw(c22.965,0.525) 24.04,0.525 ccw(c25.115,0.525) J2.2@24.355,-0.235
UART_RXD: U1.24 U5.9 | length 40.3
  Top Layer w0.203: U1.24@30.075,9.725 31.025,9.725 32.606,11.306 57.319,11.306 59.025,9.6 59.025,5.75 62,2.775 63.1,2.775 63.275,2.95 U5.9@63.275,3.575
UART_TXD: U1.4 U5.10 | length 51.6
  Top Layer w0.203: v1(24.075,7.8) 24.5,8.225 U1.4@25.225,8.225 ; v1@24.075,7.952 ccw(c24.075,8.32) 24.335,8.06 ccw(c24.595,7.8) v1@24.227,7.8 ; v1(31.5,9.325) 33.075,10.9 57.15,10.9 58.619,9.432 58.619,5.582 61.832,2.369 63.268,2.369 63.705,2.805 63.705,3.505 U5.10@63.775,3.575 ; v1@31.5,9.477 ccw(c31.5,9.845) 31.76,9.585 ccw(c32.02,9.325) v1@31.652,9.325 ; 63.705,3.049 cw(c64.001,3.049) U5.10@63.792,3.258
  Bottom Layer w0.203: v1(24.075,7.8) 24.85,7.8 26.375,9.325 v1(31.5,9.325) ; v1@24.183,7.692 cw(c24.443,7.432) 24.443,7.8 cw(c24.443,8.168) v1@24.183,7.908 ; v1@31.392,9.217 ccw(c31.132,8.957) 31.132,9.325 ccw(c31.132,9.693) v1@31.392,9.433
USB_N: J4.2 U3.3 U5.14 | length 27.2
  Top Layer w0.127: U5.14@65.475,4.775 66.025,4.775 66.085,4.835 68.173,4.835 73.514,10.175 75.775,10.175 75.975,9.975 75.975,9.475 75.202,8.702 75.223,8.702 75.981,7.944 75.981,5.469 75.66,5.148 75.66,3.284 75.525,3.15 J4.2@75.525,2.215 ; U5.14@65.818,4.732 cw(c65.923,4.627) 65.923,4.775 cw(c65.923,4.923) U5.14@65.818,4.818 ; U3.3@75.21,8.309 cw(c75.21,7.328) 75.904,8.021 ; U3.3@75.21,8.436 cw(c75.21,7.761) 75.687,8.238 ; U3.3@75.21,8.969 ccw(c75.21,9.595) U3.3@75.653,9.153 ; U3.3@75.21,9.096 ccw(c75.21,10.029) 75.869,9.369 ; J4.2@75.428,2.787 ccw(c75.195,3.02) 75.525,3.02 ccw(c75.855,3.02) J4.2@75.622,2.787 ; U3.3@75.656,8.269 cw(c76.09,8.702) 75.477,8.702 cw(c76.138,8.702) 75.67,9.17 ; 75.873,8.052 cw(c76.523,8.702) 75.604,8.702 cw(c76.572,8.702) 75.887,9.387
USB_P: J4.3 U3.2 U5.15 | length 27.9
  Top Layer w0.127: U5.15@65.475,5.275 66.05,5.275 66.109,5.216 68.016,5.216 73.356,10.556 75.933,10.556 76.356,10.133 76.356,9.5 77.154,8.702 U3.2@77.267,8.702 ; U5.15@65.818,5.232 cw(c65.923,5.127) 65.923,5.275 cw(c65.923,5.423) U5.15@65.818,5.318 ; J4.3@76.078,2.787 ccw(c75.845,3.02) 76.175,3.02 ccw(c76.505,3.02) J4.3@76.272,2.787 ; J4.3@76.175,2.215 76.175,3.125 76.041,3.26 76.041,4.991 76.362,5.312 76.362,7.927 U3.2@77.137,8.702 ; 76.459,9.397 cw(c75.764,8.702) 76.747,8.702 cw(c75.804,8.702) 76.47,8.036 ; 76.462,8.028 cw(c77.14,7.35) U3.2@77.14,8.309 ; 76.491,9.365 ccw(c77.14,10.015) U3.2@77.14,9.096 ; 76.676,9.18 cw(c76.198,8.702) 76.874,8.702 cw(c76.238,8.702) U3.2@76.687,8.253 ; 76.679,8.245 cw(c77.14,7.784) U3.2@77.14,8.436 ; U3.2@76.708,9.148 ccw(c77.14,9.581) U3.2@77.14,8.969
VCC: C10.1 C11.1 J1.1 J1.3 J5.1 J6.3 R8.2 R9.2 R10.2 U6.3 | length 70.4
  Top Layer w0.203: C11.1@9.6,45.935 9.575,45.935 C11.1@9.6,45.96
  Top Layer w0.305: 14.85,24.4 U6.3@15.925,24.4
  Top Layer w0.635: J5.1@3.836,38.861 cw(c3.077,38.102) 4.15,38.102 cw(c5.223,38.102) J5.1@4.464,38.861 ; J1.3@3.869,11.841 ccw(c3.131,12.579) 4.175,12.579 ccw(c5.219,12.579) J1.3@4.481,11.841 ; J1.1@3.869,13.769 cw(c3.131,13.031) 4.175,13.031 cw(c5.219,13.031) J1.1@4.481,13.769 ; J1.1@3.869,14.381 ccw(c3.191,15.059) 4.15,15.059 ; 4.15,15.179 ccw(c5.279,15.179) J1.1@4.481,14.381 ; J1.3@4.175,11.535 J1.1@4.175,14.075 4.15,14.1 J5.1@4.15,39.175 8.8,39.175 9.6,39.975 R9.2@9.6,41.625 R10.2@9.6,43.06 v1(10.885,43.06) ; J5.1@4.591,38.861 cw(c5.35,38.102) 5.35,39.175 cw(c5.35,40.248) J5.1@4.591,39.489 ; R8.2@9.6,47.36 9.6,45.96 C11.1@9.6,45.935 10.835,45.935 v1(10.9,46) 12.35,47.45 J6.3@15.35,47.45 ; v1(12.088,24.213) C10.1@13.325,24.213 14.188,24.213 14.375,24.4 14.85,24.4 ; J6.3@14.894,47.144 ccw(c14.156,46.406) 14.156,47.45 ccw(c14.156,48.494) J6.3@14.894,47.756
  Bottom Layer w0.635: v1(4.137,24.213) v1(12.088,24.213) ; v1(10.885,43.06) 10.885,45.89 10.9,45.905 v1(10.9,46)
pads on no net: HOLE1.1 HOLE2.1 HOLE3.1 HOLE4.1 J4.0 J4.4 MARK1.0 MARK2.0 MARK3.0 U1.1 U1.5 U1.11 U1.12 U1.15 U1.16 U1.17 U1.18 U1.20 U1.21 U1.22 U1.23 U1.25 U1.26 U1.27 U1.28 U1.29 U1.30 U1.31 U1.32 U5.3 U5.4 U5.5 U5.6 U5.7 U5.8 U5.11 U5.12

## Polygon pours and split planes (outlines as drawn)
GND on Top Layer "T Layer-GND" (solid, remove dead copper, pour order 1000): -3,-3 -3,57 87,57 87,-3 -3,-3
GND on Bottom Layer "B Layer-GND" (solid, remove dead copper, pour order 1001): -3,57 87,57 87,-3 -3,-3 -3,57

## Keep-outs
Keep-Out Layer:
  the board outline again, w0.025

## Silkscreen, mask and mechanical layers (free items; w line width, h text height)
Top Overlay:
  circle w0.203: c84,0 r1.1
  region: -6.728,102.045 -5.268,104.966 -3.807,102.045
  region: -6.167,95.314 -6.167,102.045 -4.36,102.045 -4.36,95.314 -4.664,95.314 -4.664,101.568 -5.862,101.568 -5.862,95.949 -4.664,95.949 -4.664,95.314
  lines w0.2: 2.88,37.905 2.88,37.205 2.175,36.5 2.175,22.5 3.125,21.55
  text "SMT A" at -4.664,95.949 h2.29 r90
  text "P/N:13.01.06844" at -4.524,73.454 h2.54 r90
  text "GND" at 2.812,35.267 h1.02
  text "NRST" at 2.812,32.727 h1.02
  text "INT" at 2.812,30.187 h1.02
  text "230725 Rev.B" at 85.519,28.426 h2.03 r90
  text "SDA" at 2.812,27.672 h1.02
  text "ZLG7291-EVB" at 82.979,25.321 h3.05 r90
  text "SCL" at 2.812,25.107 h1.02
  text "VCC" at 2.812,22.592 h1.02
  text "3V3" at 8.437,13.418 h1.02
  text "5V" at 8.437,10.853 h1.02
  text "SDA" at 8.411,8.313 h1.02
  text "SCL" at 8.411,5.824 h1.02
  text "INT" at 8.497,3.41 h1.02
  text "ISP" at 12.888,1.016 h1.02
  text "GND" at 15.25,0.991 h1.02
  text "3V3" at 20.196,0.922 h1.02
  text "GND" at 30.762,0.922 h1.02
  text "CLK" at 25.098,0.896 h1.02
  text "RST" at 27.968,0.896 h1.02
  text "IO" at 23.549,0.871 h1.02
  text "NRST" at 8.497,0.703 h1.02
  text "RST" at 40.747,-2.3 h1.52
  text "POWER" at 61.025,-2.3 h1.52
Bottom Overlay:
  region: 86.023,5.033 86.023,4.993 85.993,4.92 85.936,4.863 85.863,4.833 85.823,4.833 79.623,4.833 79.583,4.833 79.51,4.863 79.453,4.92 79.423,4.993 79.423,5.033 79.423,9.033 79.423,9.073 79.453,9.146 79.51,9.203 79.583,9.233 79.623,9.233 85.823,9.233 85.863,9.233 85.936,9.203 85.993,9.146 86.023,9.073 86.023,9.033
Mechanical 1:
  lines w0.025: -3,1.5 -4.5,1.5 -4.5,-3 -6.73,-3 cw(c-6.73,-1.73) -8,-1.73 -8,241.73 cw(c-6.73,241.73) -6.73,243 -4.5,243 -4.5,238.5 -3,238.5 ; -3,52.5 -4.5,52.5 -4.5,63.5 -3,63.5 ; -3,114.627 -4.5,114.627 -4.5,125.627 -3,125.627 ; -3,176.5 -4.5,176.5 -4.5,187.5 -3,187.5 ; 177,1.5 178.5,1.5 178.5,-3 180.73,-3 ccw(c180.73,-1.73) 182,-1.73 182,241.73 ccw(c180.73,241.73) 180.73,243 178.5,243 178.5,238.5 177,238.5 ; 177,52.5 178.5,52.5 178.5,63.5 177,63.5 ; 177,114.627 178.5,114.627 178.5,125.627 177,125.627 ; 177,176.5 178.5,176.5 178.5,187.5 177,187.5
  lines w0.254: -3.797,-4.808 -3.035,-4.046 -3.035,-8.491 ; 86.178,-4.833 86.94,-4.071 86.94,-8.516 ; 176.178,-4.833 176.94,-4.071 ; 176.94,-8.516 176.94,-4.071 ; 177.702,-4.833 176.94,-4.071 ; 87,0 cw(c84,0) 84,-3 0,-3 cw(c0,0) -3,0 -3,47 -3,54 cw(c0,54) 0,57 84,57 cw(c84,54) 87,54 ; 87,0 ccw(c90,0) 90,-3 174,-3 ccw(c174,0) 177,0 177,54 ccw(c174,54) 174,57 90,57 ccw(c90,54) 87,54 ; 87,0 87,54 ; 87,0 87,54 ; 87,62 ccw(c90,62) 90,59 174,59 ccw(c174,62) 177,62 177,116 ccw(c174,116) 174,119 90,119 ccw(c90,116) 87,116 ; 87,62 cw(c84,62) 84,59 0,59 cw(c0,62) -3,62 -3,116 cw(c0,116) 0,119 84,119 cw(c84,116) 87,116 ; 87,62 87,116 ; 87,62 87,116 ; 87,124 cw(c84,124) 84,121 0,121 cw(c0,124) -3,124 -3,178 cw(c0,178) 0,181 84,181 cw(c84,178) 87,178 ; 87,124 ccw(c90,124) 90,121 174,121 ccw(c174,124) 177,124 177,178 ccw(c174,178) 174,181 90,181 ccw(c90,178) 87,178 ; 87,124 87,178 ; 87,124 87,178 ; 87,186 ccw(c90,186) 90,183 174,183 ccw(c174,186) 177,186 177,240 ccw(c174,240) 174,243 90,243 ccw(c90,240) 87,240 ; 87,186 cw(c84,186) 84,183 0,183 cw(c0,186) -3,186 -3,240 cw(c0,240) 0,243 84,243 cw(c84,240) 87,240 ; 87,186 87,240 ; 87,186 87,240
  text "F" at 1.597,223.538 h12.7
  text "F" at 91.597,223.538 h12.7
  text "F" at 1.597,161.538 h12.7
  text "F" at 91.597,161.538 h12.7
  text "F" at 1.597,99.538 h12.7
  text "F" at 91.597,99.538 h12.7
  text "F" at 1.597,37.538 h12.7
  text "F" at 91.597,37.538 h12.7
  text "V-CUT" at -4.305,-8.491 h1.52 r90
  text "V-CUT" at 85.67,-8.516 h1.52 r90
  text "V-CUT" at 175.67,-8.516 h1.52 r90
Mechanical 2:
  drawing of 633 lines, arcs and shapes, not listed
  text "PCB加工工艺要求" at 237.665,115.11 h7.11
  text "mm x" at 217.269,110.386 h2.54
  text "mm" at 232.763,110.386 h2.54
  text "190" at 208.76,110.157 h2.54
  text "246" at 224.254,110.157 h2.54
  text "IPC-600  IPC-6011/12最新版本" at 262.176,110.132 h2.54
  text "IPC-Ⅱ" at 305.737,110.106 h2.54
  text "IPC-Ⅲ" at 318.437,110.106 h2.54
  text "尺寸" at 194.706,109.678 h3.81
  text "验收标准" at 245.506,109.678 h3.81
  text "FR4 TG140" at 212.646,105.052 h2.54
  text "FR4 TG170" at 235.506,105.052 h2.54
  text "生益有胶材料" at 258.366,105.052 h2.54
  text "MEGTRON6" at 281.226,105.052 h2.54
  text "其他：" at 304.086,105.052 h2.54
  text "板材" at 194.67,104.593 h3.81
  text "单面" at 212.646,99.972 h2.54
  text "2" at 230.426,99.972 h2.54
  text "4" at 248.206,99.972 h2.54
  text "6" at 265.986,99.972 h2.54
  text "8" at 283.766,99.972 h2.54
  text "10" at 301.546,99.972 h2.54
  text "板层" at 194.67,99.507 h3.81
  text "0.4mm" at 212.646,94.892 h2.54
  text "0.6mm" at 226.616,94.892 h2.54
  text "0.8mm" at 240.586,94.892 h2.54
  text "1.0mm" at 254.556,94.892 h2.54
  text "1.2mm" at 268.526,94.892 h2.54
  text "1.4mm" at 282.496,94.892 h2.54
  text "1.6mm" at 296.466,94.892 h2.54
  text "1.8mm" at 310.436,94.892 h2.54
  text "2.0mm" at 324.406,94.892 h2.54
  text "板厚" at 194.67,94.422 h3.81
  text "0.5OZ" at 243.888,89.812 h2.54
  text "1OZ" at 256.588,89.812 h2.54
  text "2OZ" at 269.288,89.812 h2.54
  text "（完成铜厚）" at 218.572,89.488 h3.3
  text "外层" at 211.555,89.329 h3.81
  text "铜厚" at 194.666,89.296 h3.81
  text "白色" at 224.076,84.732 h2.54
  text "其他：" at 241.856,84.732 h2.54
  text "丝印颜色" at 194.666,84.236 h3.81
  text "绿色" at 224.076,79.652 h2.54
  text "黑色" at 241.856,79.652 h2.54
  text "红色" at 259.636,79.652 h2.54
  text "蓝色" at 277.416,79.652 h2.54
  text "黄色" at 295.196,79.652 h2.54
  text "其他：" at 312.976,79.652 h2.54
  text "（亮光）" at 208.392,79.332 h3.3
  text "阻焊颜色" at 194.666,79.151 h3.81
  text "沉镍金 （金厚≥0.05um，镍厚≥3um）" at 224.457,74.724 h2.54
  text "无铅喷锡" at 277.416,74.572 h2.54
  text "电镀镍金" at 295.323,74.572 h2.54
  text "光板" at 312.976,74.572 h2.54
  text "其它" at 326.184,74.572 h2.54
  text "表面处理工艺" at 194.666,74.04 h3.81
  text "无" at 224.076,69.517 h2.54
  text "按键镀硬金" at 234.744,69.517 h2.54
  text "金手指" at 253.032,69.517 h2.54
  text "半孔工艺" at 270.558,69.517 h2.54
  text "FPCB补强" at 288.084,69.517 h2.54
  text "特殊工艺" at 194.666,68.98 h3.81
  text "树脂塞孔" at 291.005,64.183 h2.54
  text "电镀填孔" at 308.531,64.183 h2.54
  text "是，但双面开窗除外" at 224.076,64.158 h2.54
  text "否" at 253.159,64.158 h2.54
  text "按文件" at 270.939,64.158 h2.54
  text "是否阻焊塞孔" at 194.67,63.884 h3.81
  text "非拼板" at 224.076,59.332 h2.54
  text "拼板" at 241.856,59.332 h2.54
  text "Ver 22.10.31" at 314.754,59.103 h3.05
  text "交货方式" at 194.666,58.824 h3.81
  text "Gerber输出：英制、相对零点、抑制前导零、精度2:5" at 194.739,54.404 h3.05
  text "副边" at 317.04,52.245 h2.03
  text "NC Drill输出：英制、相对零点、抑制前导零、精度2:4" at 194.739,50.848 h3.05
  text "其他说明" at 194.612,46.403 h3.81
  text "桥连处不能添加铜皮" at 310.69,43.101 h2.03
  text "1." at 193.85,42.974 h3.05
  text "*.GM1 层为外形铣边；若有工艺副边，请在副边上增加整块平衡铜，" at 197.152,42.974 h3.05
  text "禁止使用方块状、点状图形，防机器误识别。但类似右图所示的桥连处，禁止添加平衡铜" at 197.025,40.053 h3.05
  text "2." at 193.847,36.878 h3.05
  text "请用供应商UL认证号，防火等级，CTI等级，生产周期替换板上的UR标识，且保持其位置、方向一致," at 197.152,36.878 h3.05
  text "若板内无，可在工艺副边添加; 禁止添加文件中不存在的元素，包括供应商LOGO、无铅、光学基准点等" at 197.152,33.585 h3.05
  text "R" at 323.923,31.176 h0.64
  text "3." at 193.85,30.274 h3.05
  text "若焊盘开窗与丝印油冲突，焊盘处需将丝印油掏开，不允许上盘" at 197.152,30.274 h3.05
  text "94V-0" at 325.701,29.766 h1.17
  text "标识样式>>>" at 306.626,28.75 h2.54
  text "CTI>=175" at 321.739,27.607 h2.2
  text "4." at 193.85,26.845 h3.05
  text "若存在5X15或4.4X6.6mm丝印白油块，其为激光打标用，需完整及平整；若无则忽略" at 197.152,26.845 h3.05
  text "5." at 193.85,23.416 h3.05
  text "若存在V-CUT，无特别说明时，须为双面V-CUT，角度30（+-5°），余量按以下表格执行" at 197.152,23.416 h3.05
  text "PCB厚度（mm）" at 208.099,18.971 h3.05
  text "筋厚" at 199.59,18.59 h3.05
  text "（余量）" at 198.32,15.542 h3.05
  text "0.6" at 208.099,15.415 h3.05
  text "0.8" at 214.186,15.415 h3.05
  text "1" at 221.712,15.415 h3.05
  text "1.2" at 226.387,15.415 h3.05
  text "1.6" at 232.483,15.415 h3.05
  text "2" at 239.722,15.415 h3.05
  text "2.5" at 244.66,15.415 h3.05
  text "3" at 251.914,15.415 h3.05
  text "0.16" at 207.341,11.923 h3.05
  text "0.2" at 214.199,11.923 h3.05
  text "0.3" at 220.295,11.923 h3.05
  text "0.3" at 226.286,11.923 h3.05
  text "0.4" at 232.395,11.923 h3.05
  text "0.5" at 238.587,11.923 h3.05
  text "0.5" at 244.679,11.923 h3.05
  text "最小值" at 198.193,11.859 h3.05
  text "0.5" at 250.746,11.859 h3.05
  text "0.32" at 207.351,8.43 h3.05
  text "0.4" at 214.192,8.43 h3.05
  text "0.45" at 219.529,8.43 h3.05
  text "0.5" at 226.279,8.43 h3.05
  text "0.6" at 232.458,8.43 h3.05
  text "0.7" at 238.594,8.43 h3.05
  text "0.8" at 244.683,8.43 h3.05
  text "0.8" at 250.774,8.43 h3.05
  text "最大值" at 198.193,8.303 h3.05
  text "6." at 193.85,3.985 h3.05
  text "PCB做完后，请高温烘烤进行应力释放，再整平（或重物压板烘烤），防止翘曲" at 197.152,3.985 h3.05
  text "我司生产使用无铅工艺制程" at 197.025,0.556 h3.05
  text "7." at 193.85,0.429 h3.05

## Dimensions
-4.5,243 to -6.73,-3 on Mechanical 1
-8,241.73 to 182,241.73 on Mechanical 1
